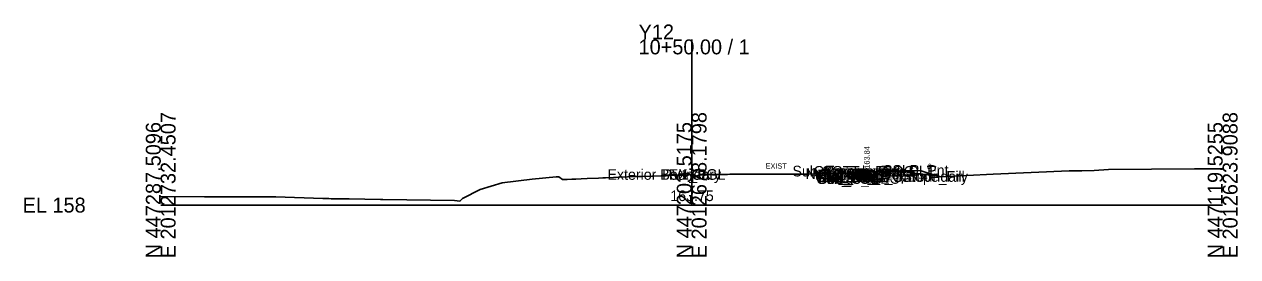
# Model space of a CAD drawing. Extents: x -26 to 1203, y -10 to 9542.
# Drawn here: x -25.7 to 202.8, y 990.3 to 1034 of the extents above; entities that cross this region are included whole.
import ezdxf

# ---------------------------------------------------------------- set-up
doc = ezdxf.new("R2010")
doc.units = 0
for name, color, linetype in [('Default', 7, 'Continuous'), ('Exist Cross Section Cell', 7, 'Continuous'), ('Exist XS Center Line Elevation Label', 7, 'Continuous'), ('Exist XS Ground Line', 7, 'Continuous'), ('Prop CMT Conc Surface', 7, 'Continuous'), ('Prop CMT Concrete Structures', 7, 'Continuous'), ('Prop CMT Pvmt Course 1', 7, 'Continuous'), ('Prop CMT Pvmt Course 1 CG', 7, 'Continuous'), ('Prop CMT Pvmt Course 2', 7, 'Continuous'), ('Prop CMT Pvmt Course 3', 7, 'Continuous'), ('Prop CMT Pvmt Surface', 7, 'Continuous'), ('Prop CMT Slope Grass', 7, 'Continuous'), ('Prop CMT Subgrade Earthwork', 7, 'Continuous'), ('Prop XS Earthwork Shape', 7, 'Continuous'), ('Prop XS Hydro Elevations', 7, 'Continuous'), ('Prop XS SE Text', 7, 'Continuous'), ('Prop XS Side Slope Text', 7, 'Continuous'), ('Scratch_Level_0', 7, 'Continuous')]:
    doc.layers.add(name, color=color, linetype=linetype)

msp = doc.modelspace()

# ---------------------------------------------------------------- linework, layer by layer
at = {"layer": 'Exist Cross Section Cell'}
for p, q in [((100, 1000), (100, 1031.13)), ((0, 1000), (100, 1000)), ((100, 1000), (200, 1000))]:
    msp.add_line(p, q, dxfattribs=at)
at = {"layer": 'Exist XS Ground Line'}
msp.add_lwpolyline([(0, 1001.61), (8.22, 1001.58), (21.67, 1001.56), (30.55, 1001.24), (30.89, 1001.23), (31.26, 1001.22), (31.66, 1001.21), (32.08, 1001.2), (32.52, 1001.19), (32.98, 1001.18), (33.43, 1001.18), (33.89, 1001.17), (34.33, 1001.17), (34.75, 1001.17), (35.14, 1001.17), (35.5, 1001.17), (41.4, 1001.05), (41.81, 1001.05), (55.35, 1000.84), (56.35, 1000.72), (56.85, 1001.22), (60.17, 1002.94), (64.3, 1004.2), (69.99, 1004.88), (74.48, 1005.28), (75, 1005.3), (75.65, 1004.79), (76.53, 1004.82), (77.45, 1004.86), (78.2, 1004.9), (79.21, 1004.94), (80.33, 1005), (82.44, 1005.09), (83.27, 1005.13), (83.74, 1005.15), (85.27, 1005.2), (86.25, 1005.24), (87.89, 1005.31), (89.21, 1005.35), (90.66, 1005.39), (92.47, 1005.45), (92.9, 1005.46), (94.28, 1005.5), (95.17, 1005.53), (96.08, 1005.56), (97.5, 1005.62), (98.05, 1005.65), (98.54, 1005.67), (98.93, 1005.44), (99.53, 1005.74), (100, 1005.75), (100.37, 1005.75), (100.97, 1005.45), (101.69, 1005.73), (102.25, 1005.73), (104.13, 1005.75), (106.75, 1005.78), (107.21, 1005.79), (109.02, 1005.81), (110.09, 1005.81), (111.35, 1005.81), (113.06, 1005.8), (114.18, 1005.79), (116.17, 1005.79), (118.96, 1005.79), (119.29, 1005.79), (120.24, 1005.8), (120.55, 1005.8), (121.95, 1005.82), (124.54, 1005.85), (125.14, 1005.85), (127.91, 1005.89), (128.59, 1005.9), (129.43, 1005.91), (129.74, 1005.91), (130.84, 1005.93), (131.42, 1005.95), (131.74, 1006.12), (132.17, 1006.34), (135.2, 1006.31), (140.1, 1006.26), (144.96, 1005.6), (146.89, 1005.32), (156.75, 1005.79), (171.12, 1006.44), (173.45, 1006.43), (175.8, 1006.49), (178.5, 1006.69), (194.68, 1006.8), (200, 1006.83)], dxfattribs=at)
at = {"layer": 'Prop CMT Conc Surface'}
msp.add_lwpolyline([(131.01, 1005.91), (133.01, 1005.84), (133.01, 1006.34), (133.51, 1006.34)], dxfattribs=at)
at = {"layer": 'Prop CMT Concrete Structures'}
for points in [[(131.01, 1005.91), (133.01, 1005.84), (133.01, 1006.34), (133.51, 1006.34)], [(133.51, 1006.34), (133.51, 1005.34), (131.01, 1005.33)], [(131.01, 1005.33), (131.01, 1005.91)]]:
    msp.add_lwpolyline(points, dxfattribs=at)
at = {"layer": 'Prop CMT Pvmt Course 1'}
for points in [[(100, 1005.75), (100, 1005.75)], [(129.74, 1005.91), (129.74, 1005.91)], [(129.74, 1005.91), (131.01, 1005.91)], [(129.74, 1005.66), (129.74, 1005.91)], [(131.01, 1005.66), (129.74, 1005.66)], [(131.01, 1005.91), (131.01, 1005.66)]]:
    msp.add_lwpolyline(points, dxfattribs=at)
at = {"layer": 'Prop CMT Pvmt Course 1 CG'}
for points in [[(131.01, 1005.33), (134.01, 1005.34), (134.34, 1005.01)], [(131.01, 1005), (131.01, 1005.33)], [(134.34, 1005.01), (131.01, 1005)]]:
    msp.add_lwpolyline(points, dxfattribs=at)
at = {"layer": 'Prop CMT Pvmt Course 2'}
for points in [[(129.74, 1005.32), (129.74, 1005.66)], [(129.74, 1005.66), (131.01, 1005.66)], [(131.01, 1005.66), (131.01, 1005.33)], [(131.01, 1005.33), (129.74, 1005.32)]]:
    msp.add_lwpolyline(points, dxfattribs=at)
at = {"layer": 'Prop CMT Pvmt Course 3'}
for points in [[(129.74, 1005.32), (131.01, 1005.33)], [(129.74, 1004.99), (129.74, 1005.32)], [(131.01, 1005), (129.74, 1004.99)], [(131.01, 1005.33), (131.01, 1005)]]:
    msp.add_lwpolyline(points, dxfattribs=at)
at = {"layer": 'Prop CMT Pvmt Surface'}
msp.add_lwpolyline([(129.74, 1005.91), (131.01, 1005.91)], dxfattribs=at)
at = {"layer": 'Prop CMT Slope Grass'}
msp.add_lwpolyline([(133.51, 1006.34), (143.01, 1006.53), (146.48, 1005.38)], dxfattribs=at)
at = {"layer": 'Prop CMT Subgrade Earthwork'}
for points in [[(129.74, 1004.99), (129.74, 1005.91)], [(131.01, 1005), (134.34, 1005.01), (135.72, 1006.39)], [(129.74, 1004.99), (131.01, 1005)], [(131.01, 1005), (129.74, 1004.99)]]:
    msp.add_lwpolyline(points, dxfattribs=at)
at = {"layer": 'Prop XS Earthwork Shape'}
for points in [[(135.2, 1006.31), (135.64, 1006.31), (134.34, 1005.01), (131.01, 1005), (129.74, 1004.99), (129.74, 1005.91), (131.01, 1005.91), (131.01, 1005.33), (133.51, 1005.34), (133.51, 1006.34)], [(131.74, 1006.12), (132.17, 1006.34), (133.01, 1006.34), (133.01, 1005.84), (131.01, 1005.91), (129.74, 1005.91), (130.84, 1005.93), (131.42, 1005.95)], [(133.51, 1005.34), (131.01, 1005.33), (131.01, 1005.91), (133.01, 1005.84), (133.01, 1006.34), (133.51, 1006.34)], [(135.64, 1006.31), (135.72, 1006.39), (143.01, 1006.53), (146.48, 1005.38), (144.96, 1005.6), (140.1, 1006.26)]]:
    msp.add_lwpolyline(points, close=True, dxfattribs=at)

# ---------------------------------------------------------------- texts
at = {"layer": 'Default'}
msp.add_text('-', height=0.0001, dxfattribs=at).set_placement((0, 1000))
at = {"layer": 'Exist Cross Section Cell'}
for s, p in [('Y12', (90, 1031.13)), ('10+50.00 / 1', (90, 1028.33)), ('EL 158', (-26, 998.6))]:
    msp.add_text(s, height=2.8, dxfattribs=at).set_placement(p)
for s, p in [('E 2012732.4507', (2.8, 990)), ('E 2012678.1798', (102.8, 990)), ('E 2012623.9088', (202.8, 990)), ('N 447287.5096', (0, 990)), ('N 447203.5175', (100, 990)), ('N 447119.5255', (200, 990))]:
    msp.add_text(s, height=2.8, rotation=90, dxfattribs=at).set_placement(p)
at = {"layer": 'Exist XS Center Line Elevation Label'}
msp.add_text('163.75', height=2, dxfattribs=at).set_placement((95.98, 1000.75))
at = {"layer": 'Prop XS Hydro Elevations'}
msp.add_text('163.84', height=1, rotation=90, dxfattribs=at).set_placement((133.51, 1006.84))
at = {"layer": 'Prop XS SE Text'}
msp.add_text('EXIST', height=1, rotation=0.2908, dxfattribs=at).set_placement((113.92, 1006.83))
at = {"layer": 'Prop XS Side Slope Text'}
msp.add_text('3:1', height=1, rotation=341.5651, dxfattribs=at).set_placement((144.23, 1006.92))
at = {"layer": 'Scratch_Level_0'}
for s, p in [('Exterior Boundary', (84.14, 1004.75)), ('PV1_PGL', (94.47, 1004.75)), ('EX CL', (95.67, 1004.75)), ('Sub_Trench_Out_DLT', (118.98, 1005.39)), ('Null Ex EOP', (121.44, 1004.91)), ('CG_Top_Face', (122.97, 1005.34)), ('CG1_Shelf_Out', (123.26, 1004.34)), ('Sub_PGL', (123.55, 1003.99)), ('CG_Bot_IE', (123.62, 1004.33)), ('PV2_PGL', (123.64, 1004.66)), ('PV3_PGL', (123.64, 1004.32)), ('Sub_OEOT', (123.78, 1004)), ('CG_Top_Gut', (123.94, 1004.84)), ('PV2_OEOT', (123.88, 1004.66)), ('PV3_OEOT', (123.88, 1004.33)), ('CG_Top_BOC', (124.49, 1005.34)), ('CG_Bot_BOC', (124.52, 1004.34)), ('PV1_OEOT', (124.44, 1004.91)), ('Sub_OEOP', (127.15, 1004.01)), ('PV1', (127.81, 1004.91)), ('Exterior Boundary', (130.62, 1004.38)), ('CSLP_Pnt', (135.88, 1005.53)), ('Slope_Fill', (139.69, 1004.38))]:
    msp.add_text(s, height=2, dxfattribs=at).set_placement(p)

doc.saveas('drawing.dxf')
